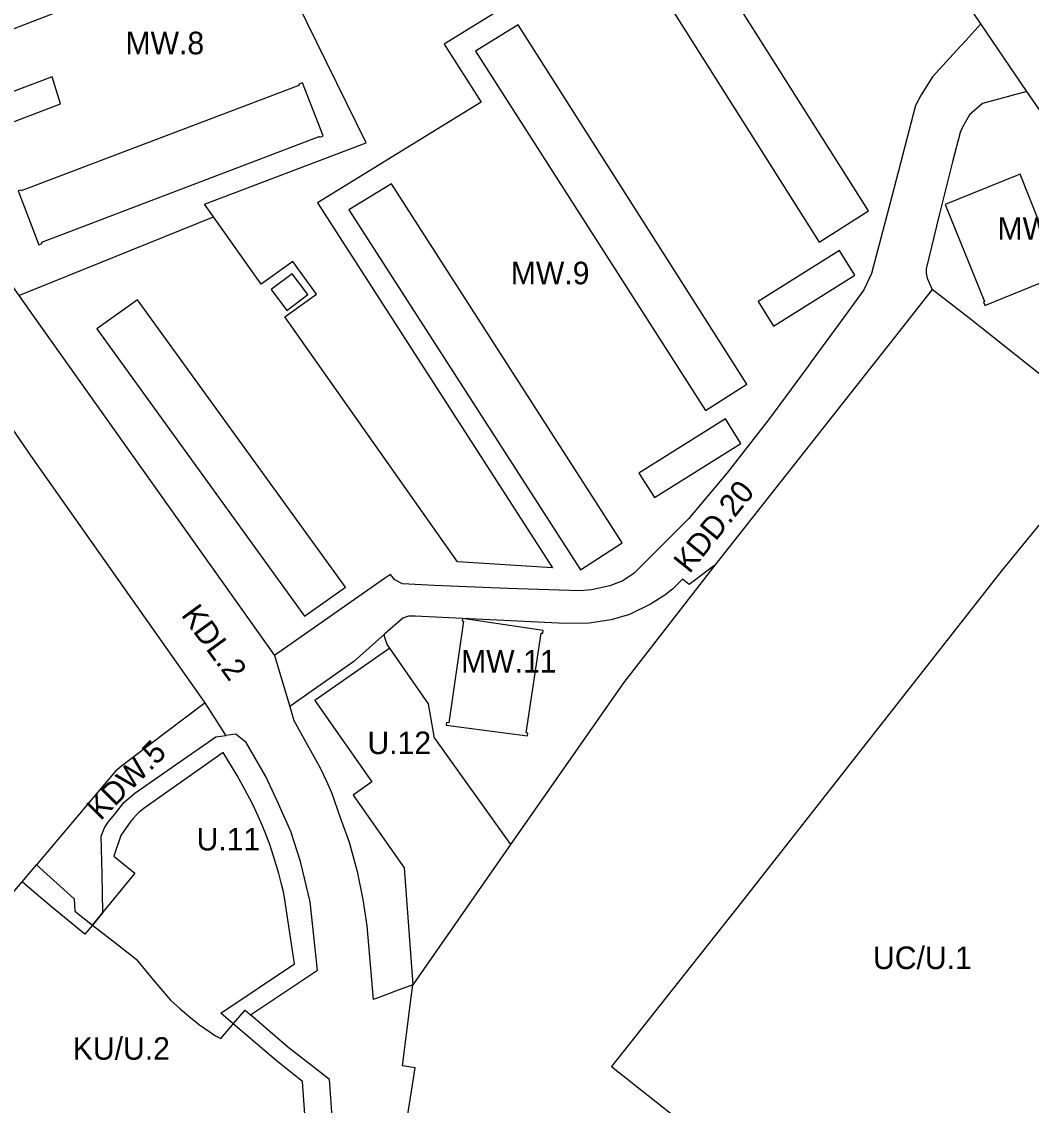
# Model space of a CAD drawing. Extents: x 7425067 to 7426806, y 5549054 to 5550619.
# Drawn here: x 7426134.9 to 7426359, y 5549894.6 to 5550135 of the extents above; entities that cross this region are included whole.
import ezdxf

# ---------------------------------------------------------------- set-up
doc = ezdxf.new("R2010")
doc.units = 0
for name, color, linetype in [('LIN_Linia Zabudowy Nieprzekraczalna', 7, 'Continuous'), ('LIN_linia zabudowy obowiązująca', 7, 'Continuous'), ('LIN_linie_rozgraniczajace', 7, 'Continuous'), ('TXT_Oznaczenia_przeznaczen', 7, 'Continuous')]:
    doc.layers.add(name, color=color, linetype=linetype)

msp = doc.modelspace()

# ---------------------------------------------------------------- linework, layer by layer
at = {"layer": 'LIN_Linia Zabudowy Nieprzekraczalna'}
for points in [[(7426216.6428, 5549996.008), (7426199.9952, 5549984.3885)], [(7426199.9952, 5549984.3885), (7426212.66, 5549966.37), (7426208.49, 5549963.44), (7426219.84, 5549947.28), (7426221.72, 5549921.35)], [(7426179.6256, 5549972.8523), (7426162.3161, 5549960.6846), (7426161.7695, 5549960.2746), (7426161.2626, 5549959.8606), (7426160.907, 5549959.5417), (7426160.4931, 5549959.1278), (7426159.6804, 5549958.2428), (7426159.1777, 5549957.6313), (7426156.9275, 5549954.4679)], [(7426195.497, 5549926.0263), (7426193.2707, 5549940.7342), (7426192.9353, 5549942.2478), (7426192.5172, 5549943.9838), (7426191.9604, 5549946.0534), (7426191.136, 5549948.9435), (7426190.0405, 5549952.2207), (7426188.9766, 5549955.1136), (7426188.325, 5549956.7558), (7426187.4164, 5549958.7955), (7426186.2645, 5549961.2034), (7426185.5865, 5549962.5771), (7426183.5838, 5549966.3085), (7426182.7591, 5549967.7474), (7426179.6256, 5549972.8523)], [(7426156.9275, 5549954.4679), (7426155.37, 5549949.87), (7426160.0286, 5549946.1419), (7426156.9991, 5549942.4393), (7426152.9394, 5549937.4584), (7426152.94, 5549937.43), (7426150.65, 5549934.62), (7426148.9562, 5549932.5519)], [(7426148.9562, 5549932.5519), (7426141.5756, 5549938.6551), (7426138.1814, 5549941.4887), (7426135.0602, 5549944.2197)], [(7426197.2527, 5549899.9387), (7426191.3836, 5549904.5357), (7426181.8851, 5549912.6806), (7426179.1045, 5549915.0649), (7426195.497, 5549926.0263)], [(7426200.381, 5549856.1483), (7426197.2527, 5549899.9387)]]:
    msp.add_lwpolyline(points, dxfattribs=at)
at = {"layer": 'LIN_linia zabudowy obowiązująca'}
for points in [[(7426263.03, 5550163.45), (7426311.94, 5550086.1), (7426322.86, 5550093.01), (7426274.07, 5550170.17), (7426263.03, 5550163.45)], [(7426114.75, 5550139.18), (7426114.61, 5550139.48), (7426113.88, 5550139.22), (7426118.19, 5550127.45), (7426118.83, 5550127.68), (7426118.76, 5550127.94), (7426181.12, 5550151.94), (7426176.84, 5550163.62), (7426176.01, 5550163.34), (7426176.01, 5550163.07), (7426114.75, 5550139.18)], [(7426286.65, 5550048.76), (7426295.85, 5550054.62), (7426245.1, 5550134.3), (7426235.61, 5550128.45), (7426286.65, 5550048.76)], [(7426126.54, 5550110.32), (7426129.37, 5550111.37), (7426143.52, 5550116.81), (7426141.66, 5550122.79), (7426127.37, 5550117.4), (7426124.51, 5550116.32), (7426121.65, 5550115.23), (7426123.74, 5550109.29), (7426126.54, 5550110.32)], [(7426139.37, 5550086.12), (7426200.98, 5550109.55), (7426201.08, 5550109.35), (7426201.82, 5550109.68), (7426197.28, 5550121.43), (7426196.4, 5550121.11), (7426196.46, 5550120.81), (7426134.83, 5550097.46), (7426134.76, 5550097.65), (7426134.12, 5550097.47), (7426138.7, 5550085.52), (7426139.43, 5550085.78), (7426139.37, 5550086.12)], [(7426355.8072, 5550100.8957), (7426339.89, 5550094.44), (7426348.61, 5550072.94), (7426348.37, 5550072.84), (7426348.7, 5550072.03), (7426365.42, 5550078.82), (7426356.51, 5550101.18)], [(7426356.51, 5550101.18), (7426355.8072, 5550100.8957)], [(7426258.94, 5550013.42), (7426268.16, 5550019.41), (7426217.01, 5550099.06), (7426207.52, 5550093.25), (7426258.94, 5550013.42)], [(7426316.4, 5550084.21), (7426298.35, 5550072.91), (7426301.74, 5550067.48), (7426319.79, 5550078.79), (7426316.4, 5550084.21)], [(7426194.93, 5550079.08), (7426190.26, 5550075.57), (7426193.74, 5550070.94), (7426198.41, 5550074.45), (7426194.93, 5550079.08)], [(7426160.64, 5550073.32), (7426151.6, 5550066.86), (7426197.71, 5550003.09), (7426206.82, 5550009.59), (7426160.64, 5550073.32)], [(7426291.11, 5550046.87), (7426271.9073, 5550034.8484), (7426275.3848, 5550029.4725), (7426294.5, 5550041.45), (7426291.11, 5550046.87)], [(7426363.71, 5550027.01), (7426352.38, 5550013.17), (7426294.43, 5549939.36), (7426265.8603, 5549903.2149)], [(7426250.68, 5549999.97), (7426232.78, 5550002.6), (7426232.71, 5550002.06), (7426232.97, 5550002.03), (7426229.71, 5549979.5), (7426229.17, 5549979.53)], [(7426247.2, 5549976.58), (7426247.28, 5549977.18), (7426246.9, 5549977.23), (7426250.25, 5549999.34), (7426250.6, 5549999.34), (7426250.68, 5549999.97)], [(7426229.17, 5549979.53), (7426229.1, 5549978.98), (7426247.2, 5549976.58)], [(7426265.8603, 5549903.2149), (7426320, 5549860.43), (7426369.9917, 5549820.9231), (7426401.5017, 5549796.0217)]]:
    msp.add_lwpolyline(points, dxfattribs=at)
at = {"layer": 'LIN_linie_rozgraniczajace'}
for points in [[(7426211.3674, 5550108.1509), (7426189.52, 5550152.53)], [(7426264.3349, 5550152.0308), (7426228.656, 5550130.0369)], [(7426347.77, 5550134.52), (7426340.56, 5550145.33)], [(7426347.77, 5550134.52), (7426344.4244, 5550130.8433)], [(7426358.0227, 5550119.5325), (7426347.77, 5550134.52)], [(7426228.656, 5550130.0369), (7426236.9302, 5550117.1182)], [(7426344.4244, 5550130.8433), (7426342.415, 5550128.635)], [(7426342.415, 5550128.635), (7426337.06, 5550122.75)], [(7426337.06, 5550122.75), (7426335.79, 5550120.75)], [(7426335.79, 5550120.75), (7426334.52, 5550118.75)], [(7426334.52, 5550118.75), (7426333.31, 5550116.4)], [(7426358.0227, 5550119.5325), (7426348.17, 5550116.84)], [(7426364.6399, 5550109.8702), (7426358.0227, 5550119.5325)], [(7426236.9302, 5550117.1182), (7426200.5463, 5550094.8432)], [(7426333.31, 5550116.4), (7426328.025, 5550096.22)], [(7426348.17, 5550116.84), (7426345.26, 5550114.33)], [(7426345.26, 5550114.33), (7426343.63, 5550111.47)], [(7426343.63, 5550111.47), (7426343.18, 5550110.4)], [(7426343.18, 5550110.4), (7426341.47, 5550103.88)], [(7426175.5216, 5550094.5189), (7426211.3674, 5550108.1509)], [(7426341.47, 5550103.88), (7426338.565, 5550092.045)], [(7426177.5218, 5550091.6923), (7426175.5216, 5550094.5189)], [(7426200.5463, 5550094.8432), (7426252.7381, 5550013.815)], [(7426328.025, 5550096.22), (7426323.5491, 5550079.1293)], [(7426134.3234, 5550074.2481), (7426177.5218, 5550091.6923)], [(7426188.06, 5550076.8), (7426177.5218, 5550091.6923)], [(7426338.565, 5550092.045), (7426335.66, 5550080.21)], [(7426195.14, 5550081.81), (7426188.06, 5550076.8)], [(7426200.39, 5550074.57), (7426195.14, 5550081.81)], [(7426335.66, 5550080.21), (7426335.62, 5550079.18)], [(7426131.0005, 5550078.9849), (7426134.3234, 5550074.2481), (7426137.4798, 5550069.7486)], [(7426323.5491, 5550079.1293), (7426321.855, 5550075.4991)], [(7426335.62, 5550079.18), (7426335.87, 5550078.1)], [(7426335.87, 5550078.1), (7426336.97, 5550075.59)], [(7426321.855, 5550075.4991), (7426317.6715, 5550069.829)], [(7426336.97, 5550075.59), (7426328.52, 5550064.86)], [(7426345.1, 5550069.3), (7426336.97, 5550075.59)], [(7426193.35, 5550069.54), (7426200.39, 5550074.57)], [(7426137.4798, 5550069.7486), (7426145.8251, 5550057.9993)], [(7426231.681, 5550015.156), (7426193.35, 5550069.54)], [(7426317.6715, 5550069.829), (7426310.1066, 5550059.5206)], [(7426365.64, 5550053), (7426345.1, 5550069.3)], [(7426328.52, 5550064.86), (7426308.655, 5550039.65)], [(7426145.8251, 5550057.9993), (7426191.0411, 5549994.3984)], [(7426309.4377, 5550058.6123), (7426300.6416, 5550046.6823)], [(7426310.1066, 5550059.5206), (7426309.4377, 5550058.6123)], [(7426137.5, 5550038.01), (7426124.64, 5550056.59)], [(7426300.6416, 5550046.6823), (7426291.4708, 5550034.9348)], [(7426308.655, 5550039.65), (7426288.79, 5550014.44)], [(7426156.565, 5550010.94), (7426137.5, 5550038.01)], [(7426291.4708, 5550034.9348), (7426282.935, 5550024.73)], [(7426282.935, 5550024.73), (7426270.8308, 5550012.6315)], [(7426252.7381, 5550013.815), (7426231.681, 5550015.156)], [(7426216.7511, 5550012.3684), (7426215.4482, 5550011.4577)], [(7426217.72, 5550011.2204), (7426216.7511, 5550012.3684)], [(7426270.8308, 5550012.6315), (7426268.3701, 5550010.9555)], [(7426288.79, 5550014.44), (7426268.5, 5549988.37)], [(7426288.79, 5550014.44), (7426283.07, 5550010.13)], [(7426175.63, 5549983.87), (7426156.565, 5550010.94)], [(7426215.4482, 5550011.4577), (7426191.0411, 5549994.3984)], [(7426219.4697, 5550010.2862), (7426217.72, 5550011.2204)], [(7426226.4557, 5550009.9479), (7426219.4697, 5550010.2862)], [(7426242.765, 5550009.295), (7426226.4557, 5550009.9479)], [(7426265.4531, 5550009.8686), (7426261.4099, 5550008.9656)], [(7426268.3701, 5550010.9555), (7426265.4531, 5550009.8686)], [(7426281.57, 5550011.355), (7426279.3584, 5550009.0917)], [(7426283.07, 5550010.13), (7426281.57, 5550011.355)], [(7426258.8164, 5550008.72), (7426242.765, 5550009.295)], [(7426261.4099, 5550008.9656), (7426258.8164, 5550008.72)], [(7426277.6545, 5550007.7999), (7426274.4671, 5550005.8089)], [(7426279.3584, 5550009.0917), (7426277.6545, 5550007.7999)], [(7426274.4671, 5550005.8089), (7426269.8159, 5550003.4833)], [(7426219.5028, 5550002.6865), (7426215.4489, 5549999.1122), (7426208.63, 5549993.1)], [(7426220.7718, 5550003.1138), (7426219.5028, 5550002.6865)], [(7426222.247, 5550003.1294), (7426220.7718, 5550003.1138)], [(7426232.78, 5550002.6), (7426222.247, 5550003.1294)], [(7426255.6329, 5550001.4691), (7426232.78, 5550002.6)], [(7426269.8159, 5550003.4833), (7426265.7762, 5550002.3073)], [(7426260.8552, 5550001.5527), (7426255.6329, 5550001.4691)], [(7426265.7762, 5550002.3073), (7426260.8552, 5550001.5527)], [(7426215.48, 5549998.59), (7426215.4489, 5549999.1122)], [(7426216.06, 5549996.85), (7426215.48, 5549998.59)], [(7426220.625, 5549990.255), (7426216.6428, 5549996.008), (7426216.06, 5549996.85)], [(7426191.0411, 5549994.3984), (7426194.4097, 5549983.1113), (7426195.3494, 5549979.9627)], [(7426208.63, 5549993.1), (7426194.4097, 5549983.1113)], [(7426225.19, 5549983.66), (7426220.625, 5549990.255)], [(7426268.5, 5549988.37), (7426243.4441, 5549952.4733)], [(7426175.63, 5549983.87), (7426166.355, 5549976.87)], [(7426179.75, 5549977.52), (7426175.63, 5549983.87)], [(7426226.53, 5549976.03), (7426225.19, 5549983.66)], [(7426195.3494, 5549979.9627), (7426198.3033, 5549974.6537)], [(7426166.355, 5549976.87), (7426157.08, 5549969.87)], [(7426169.05, 5549970.115), (7426178.04, 5549976.35)], [(7426178.04, 5549976.35), (7426180.26, 5549976.665)], [(7426180.26, 5549976.665), (7426179.75, 5549977.52)], [(7426182.48, 5549976.98), (7426180.26, 5549976.665)], [(7426184.78, 5549975.11), (7426182.48, 5549976.98)], [(7426189.13, 5549967.57), (7426184.78, 5549975.11)], [(7426198.3033, 5549974.6537), (7426201.2571, 5549969.3448)], [(7426226.53, 5549976.03), (7426243.4441, 5549952.4733)], [(7426157.08, 5549969.87), (7426155.74, 5549968.74)], [(7426160.06, 5549963.88), (7426169.05, 5549970.115)], [(7426201.2571, 5549969.3448), (7426202.4656, 5549966.6659)], [(7426155.74, 5549968.74), (7426146.97, 5549958.34)], [(7426191.89, 5549961.465), (7426189.13, 5549967.57)], [(7426202.4656, 5549966.6659), (7426203.6741, 5549963.9871)], [(7426155.87, 5549959.605), (7426157.62, 5549961.79)], [(7426157.62, 5549961.79), (7426160.06, 5549963.88)], [(7426203.6741, 5549963.9871), (7426205.6309, 5549958.5031)], [(7426154.12, 5549957.42), (7426155.87, 5549959.605)], [(7426194.65, 5549955.36), (7426191.89, 5549961.465)], [(7426146.97, 5549958.34), (7426138.2, 5549947.94)], [(7426153.34, 5549956.2), (7426154.12, 5549957.42)], [(7426205.6309, 5549958.5031), (7426207.5877, 5549953.019)], [(7426152.6, 5549954.33), (7426153.34, 5549956.2)], [(7426196.84, 5549948.69), (7426194.65, 5549955.36)], [(7426152.77, 5549945.88), (7426152.6, 5549954.33)], [(7426207.5877, 5549953.019), (7426209.3466, 5549946.4557)], [(7426243.4441, 5549952.4733), (7426221.72, 5549921.35)], [(7426131.79, 5549940.345), (7426135.0602, 5549944.2197), (7426138.2, 5549947.94)], [(7426138.2, 5549947.94), (7426146.59, 5549940.45)], [(7426198.93, 5549939.74), (7426196.84, 5549948.69)], [(7426152.94, 5549937.43), (7426152.9394, 5549937.4584), (7426152.77, 5549945.88)], [(7426209.3466, 5549946.4557), (7426210.6323, 5549940.2786)], [(7426146.59, 5549940.45), (7426146.71, 5549937.7)], [(7426210.6323, 5549940.2786), (7426211.5167, 5549934.4595)], [(7426146.71, 5549937.7), (7426150.65, 5549934.62)], [(7426200.56, 5549924.6), (7426198.93, 5549939.74)], [(7426150.65, 5549934.62), (7426152.94, 5549937.43)], [(7426150.65, 5549934.62), (7426155.505, 5549930.83)], [(7426211.5167, 5549934.4595), (7426212.9559, 5549918.0622)], [(7426155.505, 5549930.83), (7426160.36, 5549927.04)], [(7426160.36, 5549927.04), (7426164.145, 5549922.49)], [(7426185.71, 5549914.67), (7426200.56, 5549924.6)], [(7426164.145, 5549922.49), (7426167.93, 5549917.94)], [(7426221.72, 5549921.35), (7426217.89, 5549919.91)], [(7426221.14, 5549916.84), (7426221.72, 5549921.35)], [(7426214.39, 5549918.6), (7426212.9559, 5549918.0622)], [(7426217.89, 5549919.91), (7426214.39, 5549918.6)], [(7426167.93, 5549917.94), (7426170.01, 5549916.12)], [(7426170.01, 5549916.12), (7426172.09, 5549914.3)], [(7426219.44, 5549903.35), (7426221.14, 5549916.84)], [(7426172.09, 5549914.3), (7426174.415, 5549912.445)], [(7426181.79, 5549912.57), (7426181.8851, 5549912.6806), (7426184.49, 5549915.71)], [(7426184.49, 5549915.71), (7426185.71, 5549914.67)], [(7426193.92, 5549907.63), (7426185.71, 5549914.67)], [(7426174.415, 5549912.445), (7426177.915, 5549910.01)], [(7426179.09, 5549909.43), (7426181.79, 5549912.57)], [(7426177.915, 5549910.01), (7426179.09, 5549909.43)], [(7426203.24, 5549900.33), (7426193.92, 5549907.63)], [(7426222.27, 5549902.93), (7426219.44, 5549903.35)], [(7426219.97, 5549888.38), (7426222.27, 5549902.93)], [(7426203.9, 5549891), (7426203.24, 5549900.33)]]:
    msp.add_lwpolyline(points, dxfattribs=at)

# ---------------------------------------------------------------- texts
at = {"layer": 'TXT_Oznaczenia_przeznaczen'}
for s, p in [('MW.8', (7426157.969, 5550127.766)), ('MW.10', (7426351.4853, 5550086.6179)), ('MW.9', (7426243.4774, 5550076.7472)), ('MW.11', (7426232.4414, 5549990.625)), ('U.12', (7426211.6615, 5549972.535)), ('U.11', (7426173.7527, 5549951.1651)), ('UC/U.1', (7426323.8599, 5549924.8461)), ('KU/U.2', (7426146.2701, 5549904.7383))]:
    msp.add_text(s, height=5, dxfattribs=at).set_placement(p)
for s, rotation, p in [('KDD.20', 51.081167, (7426283.0973, 5550012.3834)), ('KDL.2', 306.21792, (7426170.1637, 5550003.3802)), ('KDW.5', 45.097945, (7426152.4073, 5549957.5658))]:
    msp.add_text(s, height=5, rotation=rotation, dxfattribs=at).set_placement(p)

doc.saveas('drawing.dxf')
